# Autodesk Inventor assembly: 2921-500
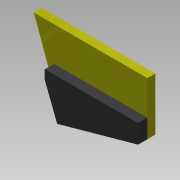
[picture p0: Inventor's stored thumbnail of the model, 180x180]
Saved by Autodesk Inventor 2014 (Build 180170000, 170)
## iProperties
Company: NHTSA/VRTC
Created: 2012-02
Part Number: 2921-500
Document SubType Name: Assembly
Designer: Mike Vanvoorhis
Project: CHILD SIDE IMPACT SLED
Description: IMPACTOR DOOR FOAM ASS'Y.
Mass: 27167.3 g
Surface Area: 10543.3 cm^2
Volume: 22797.7 cm^3
Density: 1.19167 g/cm^3
Title: IMNPACTOR DOOR FOAM ASSEMBLY
Subject: Child Side Impact Sled
Author: Dave Walker
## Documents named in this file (3)
- B:\VRTC_DWG\BIO\Non-P572\Child Side-Frontal Impact Sled\Side Impact Sled\Impactor Door Foam Assembly.iam
- B:\VRTC_DWG\BIO\Non-P572\Child Side-Frontal Impact Sled\Side Impact Sled\Impactor Door Foam.ipt
- B:\VRTC_DWG\BIO\Non-P572\Child Side-Frontal Impact Sled\Side Impact Sled\Impactor Armrest Foam.ipt
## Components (2 placed, 2 different names)
1. Impactor Door Foam:1 — Flush:1, Mate:2, Flush:2
2. Impactor Armrest Foam:1 — Flush:1, Mate:2, Flush:2
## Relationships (3: Flush 2, Mate 1)
- Flush:1: Impactor Door Foam:1 ↔ Impactor Armrest Foam:1
- Mate:2: Impactor Door Foam:1 ↔ Impactor Armrest Foam:1
- Flush:2: Impactor Door Foam:1 ↔ Impactor Armrest Foam:1
